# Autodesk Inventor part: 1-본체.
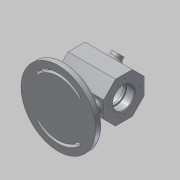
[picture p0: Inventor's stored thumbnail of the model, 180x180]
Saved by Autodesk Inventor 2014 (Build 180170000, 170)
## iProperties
Created: 2017-06
Part Number: 1-본체.
Material: Aluminum 6061
Document SubType Name: Modeling
Designer: Administrator
Density: 2.71 g/cm^3
Appearance: Aluminum - Flat
Author: Administrator
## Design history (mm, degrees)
sketch "Sketch1"
  geometry: L1 (92, -12.426)-(74.426, -30); L2 (74.426, -30)-(49.574, -30); L3 (49.574, -30)-(32, -12.426); L4 (32, -12.426)-(32, 12.426); L5 (32, 12.426)-(49.574, 30); L6 (49.574, 30)-(74.426, 30); L7 (74.426, 30)-(92, 12.426); L8 (92, 12.426)-(92, -12.426); L9 (92, -12.426)-(62, 0); L10 (92, 12.426)-(62, 0); C1 r 30 at (62, 0); 1 further point
  constraints: 20 end point, 1 centre point, 1 coincident, 1 horizontal, 1 tangent, 17 other
  dimensions: "d2" = 60 diameter of C1; "d3" = 45 deg angle of L10 L9 (derived); "d4" = 62 distance of C1.centre point (0, 0); "d5" = 92 horizontal distance of point (0, 0) L1.start
extrude "Extrusion1" new body sketch "Sketch1" stored distance "d6" = 70; taper "d7" = 0 deg
sketch "Sketch2"
  geometry: C1 r 55 at (0, 0); 1 further point
  constraints: 1 centre point, 1 coincident
  dimensions: "d8" = 110 diameter of C1
extrude "Extrusion2" join sketch "Sketch2" distance "d9" = 10; taper "d10" = 0 deg
sketch "Sketch3"
  geometry: L1 (-35, 62)-(35, 62); L2 (-35, 62)-(-35, 78); L3 (-35, 78)-(-23, 78); L4 (-23, 78)-(-23, 76); L5 (-23, 76)-(-20, 76); L6 (-20, 76)-(-20, 87); L7 (-20, 87)-(20, 87); L8 (20, 87)-(20, 76); L9 (20, 76)-(23, 76); L10 (23, 76)-(23, 78); L11 (23, 78)-(35, 78); L12 (35, 78)-(35, 62); 1 further point
  constraints: 24 end point, 11 perpendicular, 1 horizontal
  dimensions: "d12" = 12 distance of L2.end L3.end; "d14" = 3 distance of L5.end L4.end; "d16" = 40 distance of L6.end L7.end; "d17" = 3 distance of L8.end L9.end; "d19" = 32 diameter of L2.end L1; "d21" = 28 diameter of L4.end L1; "d22" = 50 diameter of L6.end L1; "d23" = 32 diameter of L11.end L1; "d24" = 28 diameter of L9.end L1; "d25" = 12 distance between parallel lines of L12 L10; "d26" = 35 distance from line of point (0, 0) L12; "d27" = 78 distance from line of point (0, 0) L11
revolve "Revolution1" sketch "Sketch3" stored, may be unused: angle "d28" = 90 deg
sketch "Sketch4"
  geometry: 5 further points
sketch "Sketch5"
  geometry: 5 further points
hole "Hole1" sketch "Sketch4" diameter "d31" = 3.242; stored, may be unused: countersink angle "d35" = 90 deg, drill point angle "d37" = 118 deg; dims "d32" = 8, "d33" = 4, "d34" = 2, "d36" = 10
hole "Hole2" sketch "Sketch5" diameter "d38" = 3.242; stored, may be unused: countersink angle "d42" = 90 deg, drill point angle "d44" = 118 deg; dims "d39" = 8, "d40" = 4, "d41" = 2, "d43" = 10
workplane "Work Plane1"
sketch "Sketch6"
  geometry: C1 r 8 at (35, 12.426); 2 further points
  constraints: 1 centre point
  dimensions: "d47" = 16 diameter of C1; "d48" = 35 horizontal distance of C1.centre point (0, 24.853); "d49" = 43.84062 distance of point (35, -31.414) C1.centre
extrude "Extrusion3" join sketch "Sketch6" stored distance "d50" = 10; taper "d51" = 0 deg
sketch "Sketch7"
  geometry: C1 r 4 at (0, 0); C2 r 8 at (0, 0) reference; 1 further point
  constraints: 1 centre point, 1 concentric
  dimensions: "d52" = 8 diameter of C1
extrude "Extrusion4" cut sketch "Sketch7" distance "d53" = 20; taper "d54" = 0 deg
sketch "Sketch8"
  geometry: C1 r 55 at (0, 0) reference; A1 r 2 centre (-30.406, 30.406) between (-31.82, 31.82) and (-28.991, 28.991); A2 r 2 centre (30.406, 30.406) between (28.991, 28.991) and (31.82, 31.82); A3 r 45 centre (0, 0) between (31.82, 31.82) and (-31.82, 31.82); A4 r 41 centre (0, 0) between (28.991, 28.991) and (-28.991, 28.991)
  constraints: 8 point on circle, 4 centre point, 4 tangent, 1 coincident, 1 concentric
  dimensions: "d62" = 2 radius of A2; "d63" = 45 radius of A3; "d64" = 60.87693 distance of A2.end A1.end
extrude "Extrusion5" cut sketch "Sketch8" distance "d65" = 7; taper "d66" = 0 deg
sketch "Sketch9"
  geometry: C1 r 55 at (0, 0) reference; A1 r 5 centre (30.406, -30.406) between (33.941, -33.941) and (26.87, -26.87); A2 r 5 centre (-30.406, -30.406) between (-26.87, -26.87) and (-33.941, -33.941); A3 r 38 centre (0, 0) between (-26.87, -26.87) and (26.87, -26.87); A4 r 48 centre (0, 0) between (-33.941, -33.941) and (33.941, -33.941)
  constraints: 8 point on circle, 4 centre point, 3 tangent, 1 coincident, 1 concentric
  dimensions: "d72" = 10 diameter of A1; "d73" = 10 diameter of A2; "d74" = 48 radius of A4; "d78" = 61.22091 distance of A1.start A2.start
extrude "Extrusion6" cut sketch "Sketch9" distance "d76" = 3; taper "d77" = 0 deg
mirror "Mirror1"
sketch "Sketch10"
  geometry: L1 (-24, 5)-(24, 5); L2 (-24, -5)-(24, -5); A1 r 5 centre (-24, 0) between (-24, 5) and (-24, -5); A2 r 5 centre (24, 0) between (24, -5) and (24, 5); 1 further point
  constraints: 4 end point, 4 point on circle, 4 tangent, 2 centre point, 1 horizontal
  dimensions: "d81" = 10 diameter of A1; "d82" = 10 diameter of A2; "d83" = 48 distance of A2.centre A1.centre; "d84" = 28.94113 distance from line of point (33.941, 33.941) L1; "d85" = 38.94113 distance from line of point (33.941, 33.941) L2
extrude "Extrusion7" join sketch "Sketch10" stored distance "d86" = 3; taper "d87" = 0 deg
chamfer "Chamfer1" distance "d88" = 1; stored, may be unused: second distance "d89" = 2, angle "d90" = 45 deg
chamfer "Chamfer2" distance "d91" = 1; stored, may be unused: second distance "d92" = 2, angle "d93" = 45 deg
chamfer "Chamfer3" distance "d96" = 1; stored, may be unused: second distance "d97" = 2, angle "d98" = 45 deg
fillet "Fillet1" dims "d94" = 3, "d95" = 0.3, "d99" = 5
sketch "Sketch11"
  geometry: 3 further points
  constraints: 1 other
  dimensions: "d100" = 35 horizontal distance of point (35, 12.426) point (0, 42.426); "d101" = 30 vertical distance of point (35, 12.426) point (0, 42.426)
emboss "Emboss1" sketch "Sketch11" dims "d12" = 12, "d14" = 3, "d16" = 40, "d17" = 3, "d19" = 32, "d21" = 28, "d22" = 50, "d23" = 32, "d24" = 28, "d25" = 12, "d26" = 35, "d27" = 78, "d102" = 0.5, "d103" = 0
body "Solid1"
other parameters: "d45" = 7, "d59" = 86
